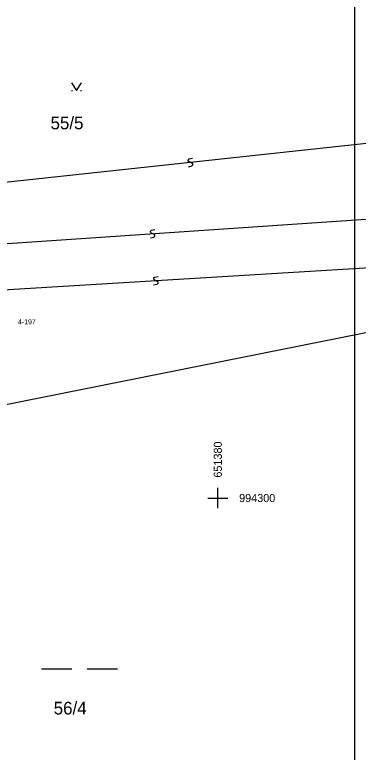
# Model space of a CAD drawing. Extents: x -651478 to -651308, y -994378 to -994071.
# Drawn here: x -651388.03 to -651374.45, y -994310.04 to -994280.91 of the extents above; entities that cross this region are included whole.
import ezdxf

# ---------------------------------------------------------------- set-up
doc = ezdxf.new("R2010")
doc.units = 0
for name, color, linetype in [('19_CISLA_BODU', 7, 'Continuous'), ('_KM', 7, 'Continuous'), ('rezy', 7, 'Continuous'), ('ROZP', 7, 'Continuous')]:
    doc.layers.add(name, color=color, linetype=linetype)

# ---------------------------------------------------------------- blocks, each defined once
blk = doc.blocks.new('Z803')
for p, q in [((-1.5, 0), (-0.3, 0)), ((0.3, 0), (1.5, 0))]:
    blk.add_line(p, q)
blk = doc.blocks.new('Z218')
for p, q in [((-0.04, 0.14), (-0.08, 0.1)), ((-0.08, 0.1), (-0.08, 0.06)), ((-0.08, 0.06), (-0.04, 0.02)), ((0.1, 0.16), (-0.04, 0.14)), ((-0.04, 0.02), (0.04, -0.02)), ((0.04, -0.14), (-0.1, -0.16)), ((0.04, -0.02), (0.08, -0.06)), ((0.08, -0.1), (0.04, -0.14)), ((0.08, -0.06), (0.08, -0.1))]:
    blk.add_line(p, q)
blk = doc.blocks.new('Z3140')
for p, q in [((-0.2, 0.3), (0, 0)), ((0, 0), (0.2, 0.3)), ((-0.2, 0), (-0.16, 0)), ((0.16, 0), (0.2, 0))]:
    blk.add_line(p, q)
blk = doc.blocks.new('Z70')
for p, q in [((0, -0.4), (0, 0.4)), ((-0.4, 0), (0.4, 0))]:
    blk.add_line(p, q)

msp = doc.modelspace()

# ---------------------------------------------------------------- linework, layer by layer
at = {"layer": '_KM'}
for p, q in [((-651342.04, -994282.52), (-651388.53, -994287.55)), ((-651397.46, -994290.57), (-651361.24, -994288.11)), ((-651396.8, -994292.29), (-651361.1, -994290.11)), ((-651394.77, -994297.58), (-651362.49, -994291.14))]:
    msp.add_line(p, q, dxfattribs=at)
at = {"layer": 'rezy'}
msp.add_line((-651374.583, -994326.69), (-651374.583, -994242.69), dxfattribs=at)

# ---------------------------------------------------------------- block references
at = {"layer": '_KM'}
for name, p in [('Z3140', (-651385.582, -994283.904)), ('Z803', (-651385.463, -994306.746))]:
    msp.add_blockref(name, p, dxfattribs=at)
for p, rotation in [((-651381.079, -994286.744), -173.82490000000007), ((-651382.575, -994289.559), -176.11450000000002), ((-651382.447, -994291.414), -176.50560000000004)]:
    msp.add_blockref('Z218', p, dxfattribs=dict(at, rotation=rotation))
at = {"layer": 'ROZP'}
msp.add_blockref('Z70', (-651380, -994300), dxfattribs=at)

# ---------------------------------------------------------------- texts
at = {"layer": '19_CISLA_BODU'}
msp.add_text('4-197', height=0.2, dxfattribs=at).set_placement((-651387.9, -994293.14))
at = {"layer": '_KM'}
for s, p in [('55/5', (-651386.611, -994285.437)), ('56/4', (-651386.485, -994308.549))]:
    msp.add_text(s, height=0.5, dxfattribs=at).set_placement(p)
at = {"layer": 'ROZP'}
msp.add_text('651380', height=0.32, rotation=90, dxfattribs=at).set_placement((-651379.84, -994299.194))
msp.add_text('994300', height=0.32, dxfattribs=at).set_placement((-651379.157, -994300.16))

doc.saveas('drawing.dxf')
